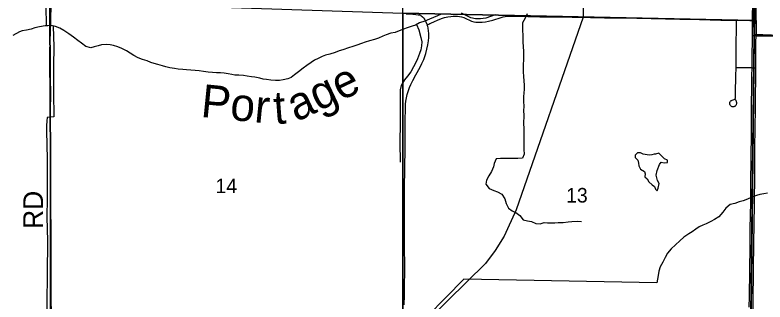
# Model space of a CAD drawing. Extents: x 0 to 39.4, y 0 to 22.
# Drawn here: x 3.277 to 5.438, y 18.59 to 19.416 of the extents above; entities that cross this region are included whole.
import ezdxf

# ---------------------------------------------------------------- set-up
doc = ezdxf.new("R2010")
doc.units = 0
for name, color, linetype in [('GM_X_Interstate_Route', 7, 'Continuous'), ('GM_X_Major_River', 7, 'Continuous'), ('GM_X_Major_River_Text', 7, 'Continuous'), ('GM_X_Minor_Lake', 7, 'Continuous'), ('GM_X_Minor_River', 7, 'Continuous'), ('GM_X_Rail_Line', 7, 'Continuous'), ('GM_X_Section', 7, 'Continuous'), ('GM_X_Section_Text', 7, 'Continuous'), ('GM_X_State_Route', 7, 'Continuous'), ('GM_X_Township_Road', 7, 'Continuous'), ('GM_X_Township_Road_Text', 7, 'Continuous')]:
    doc.layers.add(name, color=color, linetype=linetype)

msp = doc.modelspace()

# ---------------------------------------------------------------- linework, layer by layer
at = {"layer": 'GM_X_Interstate_Route'}
for points in [[(5.3867, 16.794), (5.3887, 17.3876), (5.3908, 17.7563), (5.3909, 17.7629), (5.395, 18.3937), (5.4055, 19.2651), (5.4066, 19.3573), (5.4067, 19.4006), (5.4136, 19.9268)], [(5.4136, 19.9268), (5.4067, 19.4006), (5.4066, 19.3573), (5.4055, 19.2651), (5.395, 18.3937), (5.3909, 17.7629), (5.3908, 17.7563), (5.3887, 17.3876), (5.3867, 16.794)]]:
    msp.add_lwpolyline(points, dxfattribs=at)
at = {"layer": 'GM_X_Major_River'}
for points in [[(4.5048, 19.4186), (4.4941, 19.4137), (4.4824, 19.4092), (4.471, 19.4047), (4.4573, 19.3986), (4.4428, 19.3937), (4.4307, 19.3873), (4.4212, 19.3839), (4.4068, 19.3794), (4.3961, 19.3753), (4.384, 19.3707), (4.3718, 19.3662), (4.36, 19.3636), (4.346, 19.3591), (4.3365, 19.3553), (4.324, 19.3497), (4.3129, 19.3455), (4.2981, 19.3414), (4.2856, 19.338), (4.275, 19.3342), (4.262, 19.3297), (4.2507, 19.3259), (4.2377, 19.3222), (4.2218, 19.3162), (4.2108, 19.3131), (4.1994, 19.3082), (4.1838, 19.3037), (4.172, 19.3003), (4.1618, 19.2966), (4.15, 19.2913), (4.1401, 19.2864), (4.1299, 19.2792), (4.1173, 19.2705), (4.107, 19.2633), (4.0937, 19.2523), (4.0823, 19.2444), (4.0724, 19.2365), (4.0626, 19.2327), (4.05, 19.2293), (4.039, 19.2278), (4.0276, 19.2279), (4.0144, 19.229), (4.0015, 19.2302), (3.992, 19.2318), (3.9821, 19.2341), (3.9681, 19.2371), (3.9579, 19.2387), (3.9457, 19.2402), (3.9351, 19.2418), (3.9214, 19.2426), (3.9108, 19.2434), (3.9013, 19.2449), (3.8911, 19.2472), (3.8801, 19.2488), (3.8695, 19.2496), (3.8577, 19.25), (3.8456, 19.2504), (3.8338, 19.252), (3.8198, 19.2539), (3.808, 19.2555), (3.7963, 19.2563), (3.7834, 19.2574), (3.7709, 19.2586), (3.7602, 19.2594), (3.7474, 19.2606), (3.7364, 19.2618), (3.7231, 19.2637), (3.7113, 19.2672), (3.7015, 19.2702), (3.689, 19.2741), (3.678, 19.2763), (3.6681, 19.2798), (3.6575, 19.284), (3.6439, 19.2883), (3.6321, 19.2928), (3.6192, 19.3001), (3.6086, 19.3066), (3.598, 19.3127), (3.5844, 19.3196), (3.5734, 19.3245), (3.5605, 19.3288)], [(4.6603, 19.4166), (4.647, 19.4117), (4.633, 19.4068), (4.6178, 19.4054), (4.6038, 19.4054), (4.5901, 19.4077), (4.5772, 19.4146), (4.5636, 19.4211)], [(3.5605, 19.3288), (3.551, 19.3307), (3.54, 19.3315), (3.5264, 19.33), (3.5169, 19.3274), (3.5055, 19.3244), (3.4959, 19.3216), (3.4808, 19.3256), (3.4683, 19.3355), (3.4585, 19.3424), (3.4453, 19.3523), (3.4324, 19.3622), (3.4176, 19.3717), (3.4063, 19.3786), (3.3934, 19.3828), (3.3809, 19.3859), (3.3718, 19.3855), (3.3637, 19.3852), (3.3479, 19.3826), (3.3345, 19.3792), (3.3239, 19.3758), (3.3106, 19.3724), (3.2973, 19.3702), (3.2905, 19.3676), (3.2707, 19.357)]]:
    msp.add_lwpolyline(points, dxfattribs=at)
at = {"layer": 'GM_X_Minor_Lake'}
msp.add_line((5.1223, 19.0161), (5.1185, 19.0161), dxfattribs=at)
msp.add_lwpolyline([(5.1185, 19.0161), (5.1121, 19.0138), (5.1037, 19.0127), (5.087, 19.0158), (5.0787, 19.0196), (5.0707, 19.0197), (5.0639, 19.0128), (5.0638, 19.006), (5.071, 18.9988), (5.0733, 18.99), (5.074, 18.9817), (5.0789, 18.9722), (5.0903, 18.9657), (5.0925, 18.9588), (5.0917, 18.9505), (5.0986, 18.9444), (5.1031, 18.9364), (5.1129, 18.9276), (5.1197, 18.9223), (5.1224, 18.9147), (5.1269, 18.9105), (5.1303, 18.9177), (5.133, 18.931), (5.1281, 18.9401), (5.124, 18.9557), (5.1271, 18.9686), (5.1336, 18.9864), (5.1385, 18.9929), (5.1476, 18.991), (5.1571, 18.9913), (5.1572, 18.9981), (5.1477, 19.0023), (5.1386, 19.0115), (5.1318, 19.0183), (5.1223, 19.0161)], dxfattribs=at)
at = {"layer": 'GM_X_Minor_River'}
for points in [[(3.3676, 19.3853), (3.367, 19.4425), (3.3691, 19.4938), (3.3686, 19.5948), (3.3692, 19.6632), (3.3704, 19.7995), (3.3707, 19.9101), (3.3716, 19.9492), (3.3726, 20.005), (3.3751, 20.0783)], [(4.7522, 19.4198), (4.7464, 19.4069), (4.7392, 19.3936), (4.7391, 19.3811), (4.7395, 19.3712), (4.7398, 19.3583), (4.7402, 19.3488), (4.7401, 19.3389), (4.7412, 19.3249), (4.7416, 19.3123), (4.7415, 19.2865), (4.7414, 19.2743), (4.741, 19.2618), (4.7414, 19.2523), (4.7421, 19.2394), (4.7432, 19.2272), (4.7435, 19.2143), (4.7435, 19.2018), (4.7427, 19.1919), (4.7423, 19.1809), (4.7422, 19.1676), (4.7426, 19.1539), (4.7422, 19.1407), (4.7425, 19.1277), (4.7424, 19.1034), (4.7428, 19.0909), (4.7431, 19.0768), (4.7427, 19.0666), (4.743, 19.0541), (4.743, 19.0396), (4.7433, 19.0294), (4.7437, 19.0157), (4.7394, 19.0043), (4.7258, 19.0032), (4.7125, 19.0029), (4.7, 19.0029), (4.6878, 19.0033), (4.6761, 19.0037), (4.6628, 19.0026), (4.6574, 18.989), (4.6555, 18.9795), (4.6502, 18.9658), (4.6418, 18.9533), (4.6357, 18.9408), (4.6334, 18.929), (4.6428, 18.9172), (4.6561, 18.9107), (4.6674, 18.9073), (4.6796, 18.9008), (4.6882, 18.8871), (4.692, 18.8738), (4.6992, 18.8601), (4.7094, 18.8528), (4.7196, 18.8475), (4.731, 18.8387), (4.7408, 18.8269), (4.7533, 18.8238), (4.765, 18.8215), (4.7772, 18.8162), (4.7897, 18.815), (4.8015, 18.8191), (4.8113, 18.8184), (4.8216, 18.8179), (4.8322, 18.8179), (4.8417, 18.8187), (4.8565, 18.8194), (4.8705, 18.8205), (4.8815, 18.8223), (4.8986, 18.8227), (4.9092, 18.8222)], [(3.3869, 19.3844), (3.3886, 19.3243), (3.3881, 19.2696), (3.3882, 19.1918), (3.3891, 19.123), (3.3698, 19.1216), (3.3686, 19.1117), (3.3678, 19.0973), (3.3681, 19.0825), (3.3702, 19.0012), (3.3696, 18.9313), (3.3694, 18.8872), (3.3685, 18.8356), (3.3706, 18.7653), (3.3699, 18.6722), (3.3689, 18.586), (3.3674, 18.4869), (3.3689, 18.4572)], [(4.4335, 19.3888), (4.4405, 19.3732), (4.4465, 19.3519), (4.4487, 19.3386), (4.448, 19.3276), (4.446, 19.3155), (4.4426, 19.3052), (4.4368, 19.2897), (4.4296, 19.2757), (4.425, 19.2669), (4.417, 19.2529), (4.4075, 19.2404), (4.3995, 19.2298), (4.3899, 19.2131), (4.3865, 19.201), (4.3867, 19.1664), (4.3865, 19.1056), (4.3856, 19.049), (4.3869, 18.9924)], [(5.4452, 18.9035), (5.4342, 18.902), (5.4228, 18.8998), (5.4129, 18.8967), (5.3996, 18.8922), (5.3871, 18.8866), (5.3749, 18.8813), (5.3635, 18.8783), (5.351, 18.8741), (5.3377, 18.8708), (5.3248, 18.8605), (5.3164, 18.8484), (5.3046, 18.8351), (5.2924, 18.8272), (5.2818, 18.8223), (5.2685, 18.8151), (5.2582, 18.811), (5.2484, 18.8064), (5.2385, 18.7996), (5.2282, 18.7917), (5.2183, 18.7864), (5.2043, 18.7766), (5.1921, 18.7667), (5.1799, 18.755), (5.1677, 18.7429), (5.1571, 18.7304), (5.1502, 18.7186), (5.1437, 18.705), (5.1361, 18.6917), (5.1315, 18.6792), (5.1295, 18.6666), (5.1261, 18.645)], [(5.1261, 18.645), (4.5703, 18.6557), (4.4131, 18.4963)]]:
    msp.add_lwpolyline(points, dxfattribs=at)
at = {"layer": 'GM_X_Rail_Line'}
for points in [[(4.9299, 20.9), (4.9207, 20.2492), (4.9136, 19.4102), (4.7206, 18.8553), (4.6861, 18.7801), (4.66, 18.7382), (4.6327, 18.7007), (4.4144, 18.4874), (4.369, 18.4419), (4.3263, 18.3862), (4.2933, 18.3287), (4.2793, 18.2799), (4.2724, 18.2363), (4.2649, 18.1427), (4.2497, 17.419), (4.2467, 16.9177), (4.235, 16.198), (4.2196, 15.6628), (4.2092, 15.5913), (4.1936, 15.4989), (4.1313, 15.1291), (4.1146, 15.0383)], [(5.3695, 15.387), (5.386, 16.3854), (5.3967, 18.3974), (5.4127, 19.8659), (5.4216, 20.4077), (5.4296, 20.9)]]:
    msp.add_lwpolyline(points, dxfattribs=at)
at = {"layer": 'GM_X_Section'}
for points in [[(4.4054, 20.4323), (5.4199, 20.4099), (5.4196, 20.3595), (5.4059, 19.4006), (4.394, 19.4215)], [(5.4196, 20.3595), (6.4661, 20.3227), (6.4302, 19.3208), (5.4065, 19.3604), (5.4059, 19.4006)], [(2.3842, 19.4785), (2.7709, 19.4617), (3.377, 19.4549), (3.3817, 18.4522), (2.3742, 18.4805)], [(3.377, 19.4549), (4.394, 19.4215), (4.3942, 18.4237), (3.3817, 18.4522)], [(4.394, 19.4215), (5.4059, 19.4006), (5.4065, 19.3604), (5.3953, 18.3924), (4.3942, 18.4237)], [(5.4065, 19.3604), (6.4302, 19.3208), (6.4032, 18.3261), (5.3956, 18.3552), (5.3953, 18.3924)]]:
    msp.add_lwpolyline(points, close=True, dxfattribs=at)
at = {"layer": 'GM_X_State_Route'}
for points in [[(5.4123, 19.4), (5.4126, 19.4193), (5.4127, 19.4535), (5.4142, 19.584), (5.4148, 19.6354)], [(5.3921, 18.5753), (5.3927, 18.6064), (5.3947, 18.7525), (5.3949, 18.7929), (5.3949, 18.8022), (5.3965, 18.8768), (5.3967, 18.9327), (5.3978, 19.0042), (5.3986, 19.0757), (5.3991, 19.1441), (5.4, 19.2218), (5.4, 19.2404), (5.4004, 19.2647), (5.4005, 19.2715), (5.4005, 19.287), (5.4013, 19.3569), (5.4017, 19.3865), (5.4018, 19.4001), (5.4024, 19.4611)], [(5.4118, 19.3567), (5.412, 19.382), (5.4123, 19.4)], [(5.4025, 18.5178), (5.4032, 18.6018), (5.4043, 18.6701), (5.4048, 18.7074), (5.4052, 18.7354), (5.4056, 18.7727), (5.4063, 18.8007), (5.4066, 18.8287), (5.4073, 18.8566), (5.4084, 18.9747), (5.4088, 19.0369), (5.4094, 19.0866), (5.4099, 19.1519), (5.4109, 19.2644), (5.4112, 19.2887), (5.4116, 19.3385), (5.4118, 19.3567)]]:
    msp.add_lwpolyline(points, dxfattribs=at)
at = {"layer": 'GM_X_Township_Road'}
for p, q in [((5.4069, 19.4), (5.4123, 19.4)), ((5.4013, 19.3569), (5.4068, 19.3568)), ((5.4068, 19.3568), (5.4118, 19.3567)), ((5.4057, 19.2645), (5.4109, 19.2644))]:
    msp.add_line(p, q, dxfattribs=at)
for points in [[(3.3791, 18.5704), (3.3791, 18.6052), (3.3794, 18.6456), (3.3795, 18.7059), (3.3794, 18.7575), (3.3793, 18.7842), (3.3794, 18.8104), (3.3795, 18.8489), (3.3797, 18.9079), (3.3797, 18.9254), (3.3796, 18.9508), (3.3798, 18.9788), (3.3799, 18.9981), (3.3796, 19.0317), (3.3794, 19.0615), (3.3794, 19.0969), (3.3791, 19.1187), (3.3797, 19.156), (3.38, 19.1759), (3.3803, 19.1951), (3.3799, 19.2094), (3.3798, 19.2155), (3.3796, 19.2206), (3.3794, 19.2231), (3.3784, 19.2323), (3.3777, 19.2382), (3.3774, 19.2404), (3.3773, 19.2434), (3.3772, 19.2458), (3.377, 19.251), (3.3772, 19.2808), (3.3776, 19.3131), (3.378, 19.3361), (3.3794, 19.3727), (3.38, 19.3919), (3.3806, 19.4139), (3.3818, 19.4524)], [(4.4037, 19.4193), (4.4109, 19.4192), (4.4234, 19.4186), (4.4322, 19.418), (4.4388, 19.4171), (4.4419, 19.4165), (4.4448, 19.4155), (4.4476, 19.4141), (4.4501, 19.4123), (4.4524, 19.4103), (4.4544, 19.4079), (4.4561, 19.4053), (4.4577, 19.4024), (4.4606, 19.3968), (4.4629, 19.3922), (4.464, 19.3897), (4.4649, 19.3875)], [(4.4649, 19.3875), (4.4689, 19.3895), (4.4725, 19.3913), (4.4752, 19.3927), (4.4856, 19.3977), (4.4942, 19.4014), (4.5058, 19.4058), (4.5147, 19.4086), (4.5238, 19.4108), (4.533, 19.4123), (4.5392, 19.4129), (4.5454, 19.4131), (4.5516, 19.4129), (4.5578, 19.4121), (4.5638, 19.4107), (4.5697, 19.4087), (4.5782, 19.4049), (4.5867, 19.401), (4.5925, 19.3987), (4.5984, 19.397), (4.6045, 19.3958), (4.6107, 19.3952), (4.6169, 19.3952), (4.6231, 19.3956), (4.6323, 19.3968), (4.6415, 19.3986), (4.6536, 19.4016), (4.6773, 19.4091), (4.6833, 19.4106), (4.6894, 19.4117), (4.6956, 19.4125), (4.7049, 19.4129), (4.7235, 19.4128), (4.7546, 19.4121), (4.7888, 19.4114), (4.8292, 19.4106), (4.882, 19.4099), (4.9348, 19.409), (4.9752, 19.4085), (5.0684, 19.4067), (5.1927, 19.4045), (5.2487, 19.4033), (5.2797, 19.4025), (5.3108, 19.4018), (5.3512, 19.401), (5.3553, 19.4009)], [(4.3982, 18.582), (4.3987, 18.6094), (4.3993, 18.6373), (4.3997, 18.6777), (4.3999, 18.6994), (4.3996, 18.7429), (4.3995, 18.7584), (4.3996, 18.7832), (4.3993, 18.8205), (4.3991, 18.8485), (4.3991, 18.8765), (4.3996, 18.92), (4.4002, 18.9728), (4.4007, 19.035), (4.4014, 19.1189), (4.4016, 19.1407), (4.4024, 19.1594), (4.4032, 19.1687), (4.4047, 19.178), (4.4068, 19.1871), (4.4105, 19.1991), (4.4136, 19.2079), (4.4172, 19.2166), (4.4227, 19.2278), (4.4316, 19.2442), (4.4438, 19.2659), (4.4494, 19.2769), (4.4544, 19.2882), (4.4577, 19.2969), (4.4605, 19.3058), (4.4636, 19.3177), (4.466, 19.3299), (4.4679, 19.3422), (4.4689, 19.3514), (4.4692, 19.3575), (4.4691, 19.3637), (4.4685, 19.3698), (4.467, 19.3792), (4.4661, 19.3836), (4.4649, 19.3875)], [(5.3543, 19.2648), (5.3545, 19.2745), (5.3546, 19.295), (5.3547, 19.3164), (5.3548, 19.3275), (5.355, 19.3428), (5.355, 19.346), (5.3551, 19.3653), (5.3552, 19.3804), (5.3553, 19.3928), (5.3553, 19.4009)], [(5.3553, 19.4009), (5.3941, 19.4001), (5.4018, 19.4001)], [(5.4018, 19.4001), (5.4059, 19.4), (5.4069, 19.4)], [(5.4123, 19.4), (5.412, 19.382), (5.4118, 19.3567)], [(5.4118, 19.3567), (5.4254, 19.3565), (5.4532, 19.3559), (5.4811, 19.3556), (5.5182, 19.3547), (5.5584, 19.3535), (5.5923, 19.3525), (5.6355, 19.3511), (5.654, 19.35), (5.672, 19.3493)], [(5.353, 19.191), (5.3531, 19.206), (5.3537, 19.2278), (5.3538, 19.2378), (5.354, 19.2465), (5.3542, 19.2588), (5.3543, 19.2648)], [(5.3543, 19.2648), (5.361, 19.2647), (5.3898, 19.2647), (5.3995, 19.2647), (5.4004, 19.2647)], [(5.4004, 19.2647), (5.4027, 19.2646), (5.4057, 19.2645)], [(5.3512, 19.1739), (5.3524, 19.1724), (5.3532, 19.1713), (5.3538, 19.1701), (5.3545, 19.1683), (5.3549, 19.1666), (5.3553, 19.165), (5.3554, 19.1633), (5.3554, 19.161), (5.355, 19.1589), (5.3545, 19.1575), (5.3538, 19.1561), (5.3529, 19.1549), (5.3517, 19.1539), (5.3503, 19.1531), (5.3489, 19.1525), (5.3474, 19.1522), (5.3458, 19.152), (5.344, 19.1521), (5.3427, 19.1524), (5.3412, 19.153), (5.34, 19.1538), (5.3389, 19.1549), (5.3379, 19.1561), (5.3372, 19.1575), (5.3367, 19.1589), (5.3364, 19.1605), (5.3363, 19.1621), (5.3365, 19.1637), (5.3368, 19.1651), (5.3374, 19.1666), (5.3382, 19.1679), (5.3393, 19.169), (5.3404, 19.1699), (5.3418, 19.1706), (5.3433, 19.1712), (5.3463, 19.1721), (5.3493, 19.1732), (5.3502, 19.1737), (5.3509, 19.1742), (5.3517, 19.1751), (5.3525, 19.1764), (5.3529, 19.1779), (5.353, 19.181), (5.353, 19.191)]]:
    msp.add_lwpolyline(points, dxfattribs=at)

# ---------------------------------------------------------------- texts
at = {"layer": 'GM_X_Major_River_Text'}
for s, height, rotation, p in [('age', 0.09475, 25.323, (4.0875, 19.1077)), ('Por', 0.09474, 354.3251, (3.8102, 19.1232)), ('t', 0.0947, 4.3249, (4.0251, 19.1016))]:
    msp.add_text(s, height=height, rotation=rotation, dxfattribs=at).set_placement(p)
at = {"layer": 'GM_X_Section_Text'}
for s, p in [('14', (3.8547, 18.9035)), ('13', (4.8647, 18.8765))]:
    msp.add_text(s, height=0.04186, rotation=0, dxfattribs=at).set_placement(p)
at = {"layer": 'GM_X_Township_Road_Text'}
msp.add_text('RD', height=0.05682, rotation=90, dxfattribs=at).set_placement((3.3578, 18.8006))

doc.saveas('drawing.dxf')
